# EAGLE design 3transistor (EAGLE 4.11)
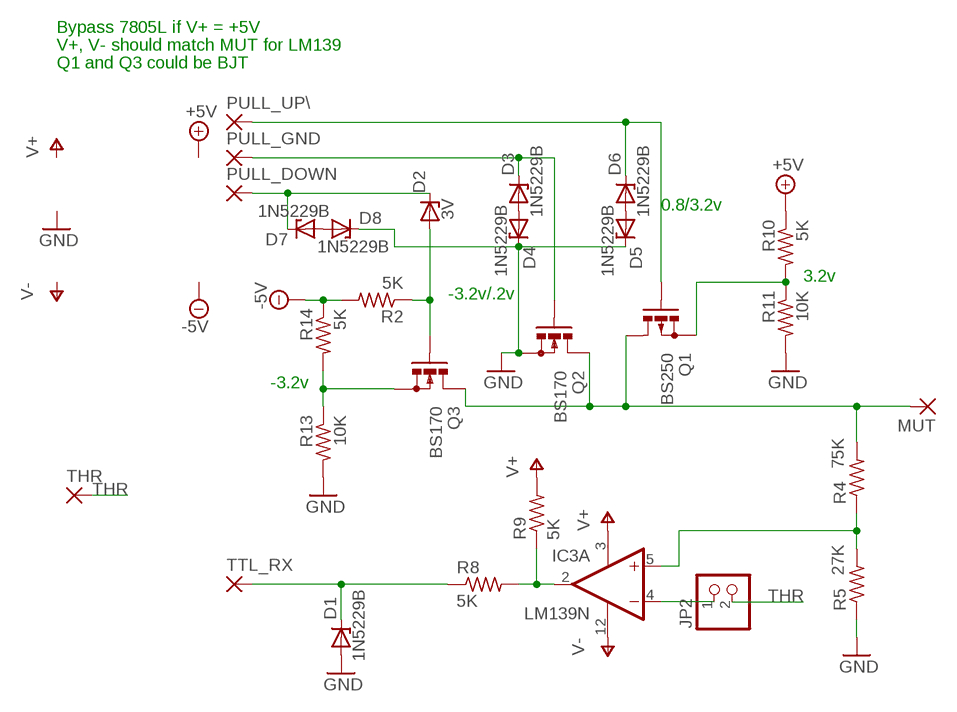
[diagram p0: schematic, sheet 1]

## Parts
D1  1N5229B  ZENER-DIODEZD-2.5  [ZDIO-2.5]
D2  3V  ZENER-DIODEZD-2.5  [ZDIO-2.5]
D3  1N5229B  ZENER-DIODEZD-2.5  [ZDIO-2.5]
D4  1N5229B  ZENER-DIODEZD-2.5  [ZDIO-2.5]
D5  1N5229B  ZENER-DIODEZD-2.5  [ZDIO-2.5]
D6  1N5229B  ZENER-DIODEZD-2.5  [ZDIO-2.5]
D7  1N5229B  ZENER-DIODEZD-2.5  [ZDIO-2.5]
D8  1N5229B  ZENER-DIODEZD-2.5  [ZDIO-2.5]
IC3  LM139N  LM339N  [DIL14]
JP2  PINHD-1X2  [1X02]
MUT  1,6/0,9  [1,6/0,9]
PULL_DOWN  1,6/0,9  [1,6/0,9]
PULL_GND  1,6/0,9  [1,6/0,9]
PULL_UP\  1,6/0,9  [1,6/0,9]
Q1  BS250  [SOT54E]
Q2  BS170  [SOT54E]
Q3  BS170  [SOT54E]
R2  5K  R-US_0207/2V  [0207/2V]
R4  75K  R-US_0207/2V  [0207/2V]
R5  27K  R-US_0207/2V  [0207/2V]
R8  5K  R-US_0207/2V  [0207/2V]
R9  5K  R-US_0207/2V  [0207/2V]
R10  5K  R-US_0207/2V  [0207/2V]
R11  10K  R-US_0207/2V  [0207/2V]
R13  10K  R-US_0207/2V  [0207/2V]
R14  5K  R-US_0207/2V  [0207/2V]
THR  1,6/0,9  [1,6/0,9]
TTL_RX  1,6/0,9  [1,6/0,9]

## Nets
+5V: R10.1
-5V: R2.2 R14.1
GND: D1.A D4.C D5.C D8.C Q2.S R5.1 R11.2 R13.2
N$1: MUT.1(P) Q1.D Q2.D Q3.D R4.2
N$2: D2.A Q3.G R2.1
N$3: D3.C PULL_GND.1(P) Q2.G
N$4: D2.C D7.C PULL_DOWN.1(P)
N$5: Q1.S R10.2 R11.1
N$6: D5.A D6.A
N$7: IC3.5(A:+IN) R4.1 R5.2
N$8: IC3.4(A:-IN) JP2.1
N$9: IC3.2(A:OUT) R8.2 R9.1
N$10: D6.C PULL_UP\.1(P) Q1.G
N$11: D3.A D4.A
N$12: D1.C R8.1 TTL_RX.1(P)
N$15: D7.A D8.A
N$16: Q3.S R13.1 R14.2
THR: JP2.2 THR.1(P)
V+: IC3.3(P:V+) R9.2
V-: IC3.12(P:GND)
Unconnected: IC3.1(B:OUT) IC3.6(B:-IN) IC3.7(B:+IN) IC3.8(C:-IN) IC3.9(C:+IN) IC3.10(D:-IN) IC3.11(D:+IN) IC3.13(D:OUT) IC3.14(C:OUT)

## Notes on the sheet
- Bypass 7805L if V+ = +5V
- V+, V- should match MUT for LM139
- Q1 and Q3 could be BJT
- 0.8/3.2v
- 3.2v
- -3.2v/.2v
- -3.2v

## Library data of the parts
D1-D8 = diode:ZENER-DIODE: Z-Diode
IC3 = linear:LM339: Low Power Low Offset Voltage Quad Comparators with open collector; LM139/LM239/LM339/LM2901/LM3302
JP2 = pinhead:PINHD-1X2: PIN HEADER
MUT PULL_DOWN PULL_GND PULL_UP\ THR TTL_RX = wirepad:1,6/0,9: THROUGH-HOLE PAD
Q1 = transistor-small-signal:BS250: P-CHANNEL MOS FET
Q2 Q3 = transistor-small-signal:BS170: N-CHANNEL MOS FET
R2 R4 R5 R8-R11 R13 R14 = rcl:R-US_: RESISTOR, American symbol

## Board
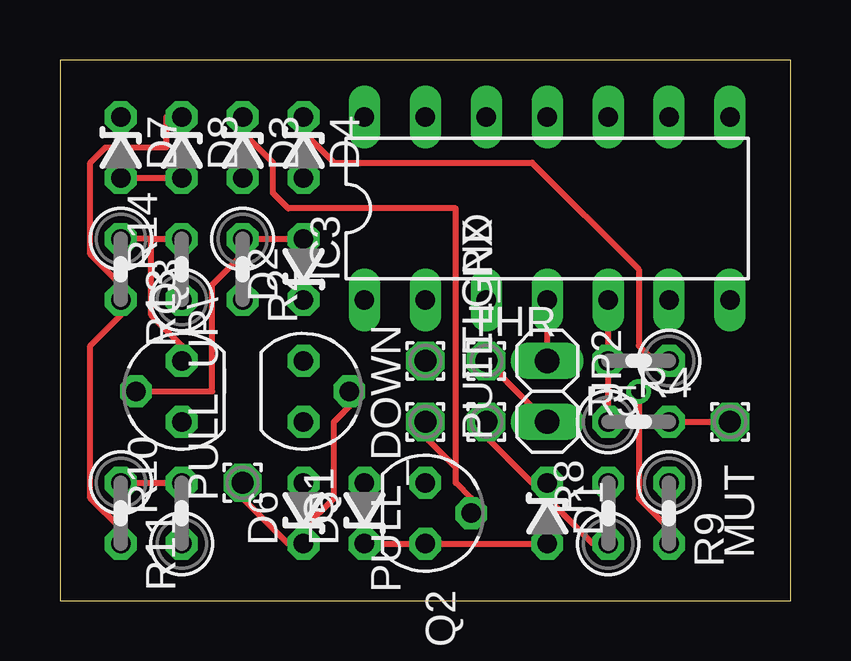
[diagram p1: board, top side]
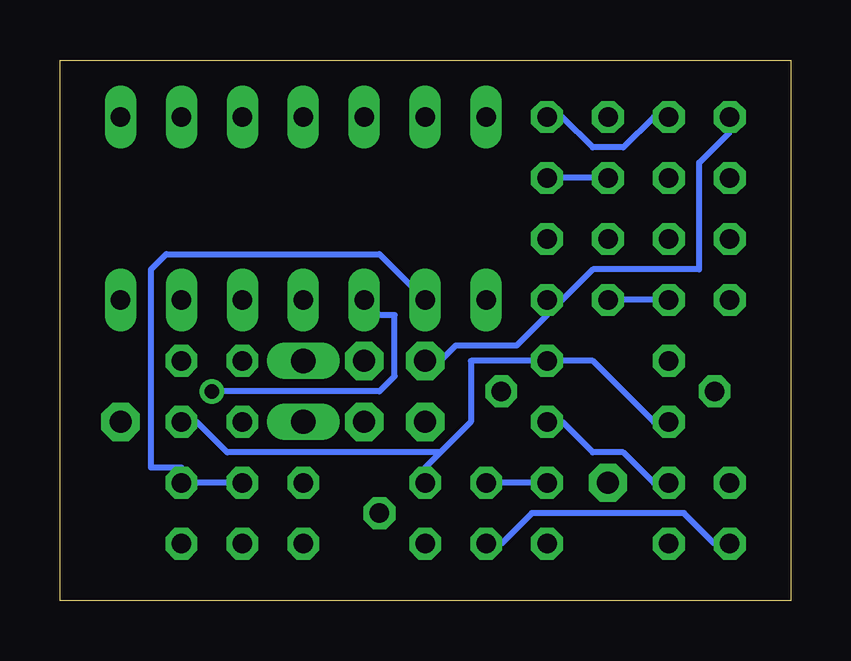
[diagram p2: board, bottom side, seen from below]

Size 30.46 x 22.53 mm. Coordinates in mm from the lower left corner, seen from the top.
Outline: 0,0 30.46,0 30.46,22.53 0,22.53 0,0
Copper layers (1*16): Top 0.035mm / dielectric 1.5mm / Bottom 0.035mm
Design rules "default": minimum track width 10mil, minimum drill 24mil, track to track 8mil, track to pad 8mil, pad to pad 8mil, via to via 8mil, smd to smd 8mil, copper to edge 40mil, drill to drill 8mil, minimum pad ring 10mil, minimum via ring 8mil, stop-mask expansion 4mil, vias tented up to drill 0mil, thermal gap 10mil

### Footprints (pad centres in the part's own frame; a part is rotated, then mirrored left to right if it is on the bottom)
ZDIO-2.5 = drill 0.813 octagon: A 1.27,0; C -1.27,0
DIL14 = drill 0.813 long: 1 -7.62,-3.81; 2 -5.08,-3.81; 3 -2.54,-3.81; 4 0,-3.81; 5 2.54,-3.81; 6 5.08,-3.81; 7 7.62,-3.81; 8 7.62,3.81; 9 5.08,3.81; 10 2.54,3.81; 11 0,3.81; 12 -2.54,3.81; 13 -5.08,3.81; 14 -7.62,3.81
1X02 = drill 1.016 long: 1 -1.27,0; 2 1.27,0
1,6/0,9 = drill 0.914 pad 1.6 octagon: 1 0,0
SOT54E = drill 0.813 octagon: D -1.27,0; G 0,1.905; S 1.27,0
0207/2V = drill 0.813 octagon: 1 -1.27,0; 2 1.27,0

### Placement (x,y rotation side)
D1  20.32,3.65 270 top
D2  10.15,13.81 90 top
D3  7.62,18.89 270 top
D4  10.15,18.89 270 top
D5  12.69,3.65 90 top
D6  10.15,3.65 90 top
D7  2.54,18.89 270 top
D8  5.08,18.89 270 top
IC3  20.32,16.35 0 top
JP2  20.32,8.73 270 top
MUT  27.94,7.46 270 top
PULL_DOWN  15.23,10 270 top
PULL_GND  15.23,7.46 0 top
PULL_UP\  7.62,4.92 90 top
Q1  10.15,8.73 270 top
Q2  15.23,3.65 270 top
Q3  5.08,8.73 90 top
R2  7.62,13.81 270 top
R4  24.12,7.46 0 top
R5  24.12,10 180 top
R8  22.86,3.65 90 top
R9  25.39,3.65 270 top
R10  5.08,3.65 90 top
R11  2.54,3.65 270 top
R13  2.54,13.81 270 top
R14  5.08,13.81 90 top
THR  17.78,10 0 top
TTL_RX  17.78,7.46 90 top

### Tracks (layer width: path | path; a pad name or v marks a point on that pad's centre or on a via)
-5V
  Bottom 0.254: R14.1 5.71,12.54 6.98,12.54 R2.2
GND
  Top 0.254: D5.C 13.33,2.38 14.6,2.38 Q2.S 15.87,2.38 19.68,2.38 D1.A | R11.2 2.54,3.01 1.27,4.28 1.27,10.63 2.54,11.9 R13.2 2.54,13.17 1.27,14.44 1.27,18.25 1.9,18.89 4.44,18.89 4.44,20.16 D8.C | R5.1 24.76,10 24.12,10.63 24.12,13.81 19.68,18.25 11.42,18.25 10.15,19.52 D4.C
  Bottom 0.254: R11.2 3.17,2.38 4.44,3.65 10.79,3.65 12.06,2.38 D5.C | D8.C 5.71,20.16 6.98,18.89 8.25,18.89 9.52,20.16 D4.C
N$1
  Top 0.254: R4.2 26.03,7.46 27.3,7.46 MUT.1
  Bottom 0.254: 14.6,6.18 13.33,7.46 13.33,10 10.79,10 Q1.D 9.52,10 8.25,10 5.71,7.46 Q3.D | 14.6,6.18 15.23,5.55 Q2.D | 14.6,6.18 23.49,6.18 24.76,7.46 R4.2
N$2
  Top 0.254: Q3.G 3.81,8.73 6.34,8.73 6.34,13.17 7.62,14.44 R2.1 8.25,15.08 9.52,15.08 D2.A
N$3
  Top 0.254: 16.51,5.55 16.51,4.92 17.14,4.28 Q2.G | 16.51,5.55 15.23,6.82 PULL_GND.1 | 16.51,5.55 16.51,16.35 9.52,16.35 8.88,16.98 8.88,18.25 7.62,19.52 D3.C
N$4
  Bottom 0.254: D7.C 2.54,19.52 3.81,18.25 3.81,13.81 8.25,13.81 9.52,12.54 D2.C 10.15,11.9 11.42,10.63 13.96,10.63 14.6,10 PULL_DOWN.1
N$5
  Top 0.254: R11.1 3.17,4.92 4.44,4.92 R10.2
  Bottom 0.254: Q1.S 9.52,7.46 8.25,6.18 6.98,6.18 5.71,4.92 R10.2
N$6
  Bottom 0.254: D6.A 10.79,4.92 12.06,4.92 D5.A
N$7
  Top 0.254: R4.1 22.86,8.09 22.86,9.36 R5.2 22.86,10.63 22.86,11.27 IC3.5
N$8
  Top 0.254: IC3.4 20.32,11.27 20.32,10.63 JP2.1
N$9
  Bottom 0.254: R8.2 23.49,4.92 24.76,4.92 R9.1 25.39,5.55 26.67,5.55 26.67,13.81 26.03,14.44 17.14,14.44 15.87,13.17 IC3.2
N$10
  Top 0.254: PULL_UP\.1 7.62,4.28 9.52,2.38 D6.C 10.15,3.01 11.42,4.28 11.42,7.46 12.06,8.09 Q1.G
N$11
  Bottom 0.254: D3.A 8.25,17.62 9.52,17.62 D4.A
N$12
  Top 0.254: R8.1 22.22,2.38 20.32,4.28 D1.C 19.68,4.92 17.78,6.82 TTL_RX.1
N$15
  Top 0.254: D7.A 3.17,17.62 4.44,17.62 D8.A
N$16
  Top 0.254: 3.81,15.08 4.44,15.08 R14.2 | 3.81,15.08 3.17,15.08 R13.1 | 3.81,15.08 3.81,11.9 5.08,10.63 Q3.S
THR
  Top 0.254: JP2.2 19.68,8.09 18.41,9.36 18.41,10 THR.1
V+  (via drill 0.61)
  Top 0.254: v24.12,8.73 24.12,4.28 25.39,3.01 R9.2
  Bottom 0.254: v24.12,8.73 17.14,8.73 16.51,9.36 16.51,11.9 17.14,11.9 IC3.3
